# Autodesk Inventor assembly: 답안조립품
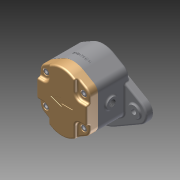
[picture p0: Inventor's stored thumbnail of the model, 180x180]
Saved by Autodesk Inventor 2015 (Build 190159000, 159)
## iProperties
Created: 2025-11
Part Number: 답안조립품
Document SubType Name: Assembly
Designer: user
Author: user
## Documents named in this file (11)
- C:\Users\user\Desktop\751103V1007\답안조립품.iam
- C:\Users\user\Desktop\751103V1007\가져온 구성요소\3자 실링\3자 실링.ipt
- C:\Users\user\Desktop\751103V1007\가져온 구성요소\6각 구멍붙이 볼트 M6x16\6각 구멍붙이 볼트 M6x16.ipt
- C:\Users\user\Desktop\751103V1007\가져온 구성요소\DU 부시\DU 부시.ipt
- C:\Users\user\Desktop\751103V1007\가져온 구성요소\가이드 블록\가이드 블록.ipt
- C:\Users\user\Desktop\751103V1007\가져온 구성요소\구동기어\구동기어.ipt
- C:\Users\user\Desktop\751103V1007\본체.ipt
- C:\Users\user\Desktop\751103V1007\가져온 구성요소\스퍼기어\스퍼기어.ipt
- C:\Users\user\Desktop\751103V1007\가져온 구성요소\실링\실링.ipt
- C:\Users\user\Desktop\751103V1007\가져온 구성요소\오일 실 16 30 7\오일 실 16 30 7.ipt
- C:\Users\user\Desktop\751103V1007\가져온 구성요소\커버\커버.ipt
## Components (11 placed, 5 different names)
1. 3자 실링:1
2. 6각 구멍붙이 볼트 M6x16:1
3. DU 부시:1
4. 가이드 블록:1
5. 구동기어:1
6. DU 부시:2
7. DU 부시:3
8. DU 부시:4
9. 6각 구멍붙이 볼트 M6x16:2
10. 6각 구멍붙이 볼트 M6x16:3
11. 6각 구멍붙이 볼트 M6x16:4
